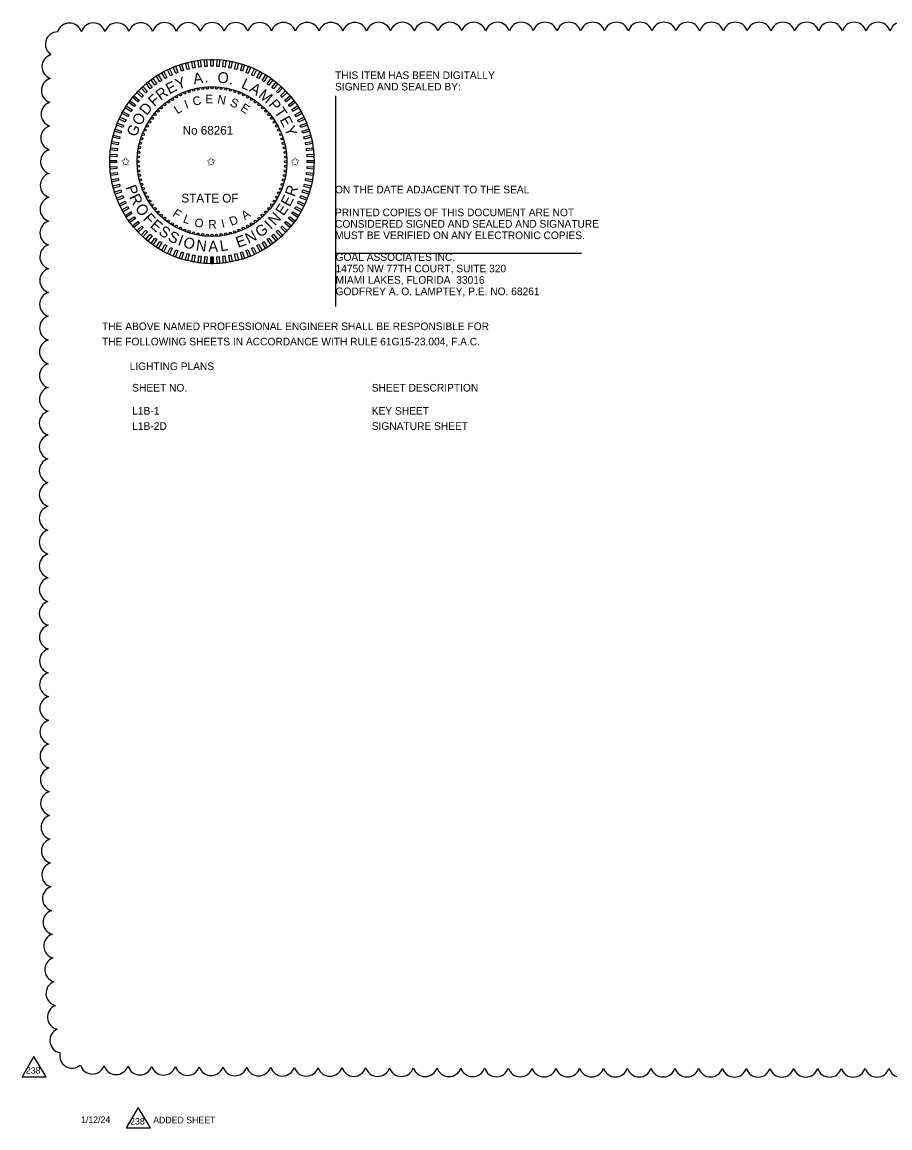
# Model space of a CAD drawing. Extents: x -811.2 to -755.6, y -2295.2 to -2235.1.
# Drawn here: x -811.23 to -803.27, y -2294.97 to -2284.82 of the extents above; entities that cross this region are included whole.
import ezdxf

# ---------------------------------------------------------------- set-up
doc = ezdxf.new("R2010")
doc.units = 0
for name, color, linetype in [('Cloud_dp', 7, 'Continuous'), ('Logo_dp', 7, 'Continuous'), ('NonPlottingEle_dp', 7, 'Continuous'), ('ScratchEle_dp', 7, 'Continuous'), ('TextMinor', 7, 'Continuous'), ('TextMisc', 7, 'Continuous'), ('TextNotes', 7, 'Continuous')]:
    doc.layers.add(name, color=color, linetype=linetype)

msp = doc.modelspace()

# ---------------------------------------------------------------- linework, layer by layer
at = {"layer": 'Cloud_dp'}
for points in [[(-811.125, -2294.318), (-811.233, -2294.506), (-811.012, -2294.506)], [(-810.168, -2294.785), (-810.276, -2294.973), (-810.055, -2294.973)]]:
    msp.add_lwpolyline(points, close=True, dxfattribs=at)
for centre, start, end in [((-810.798, -2284.941), 18.0566, 163.0566), ((-810.58, -2284.94), 17.7998, 162.7998), ((-810.362, -2284.939), 17.7187, 162.7187), ((-810.143, -2284.938), 17.6743, 162.6743), ((-809.925, -2284.937), 17.6451, 162.6451), ((-809.707, -2284.937), 17.624, 162.624), ((-809.488, -2284.936), 17.6079, 162.6079), ((-809.27, -2284.936), 17.5951, 162.5951), ((-809.052, -2284.936), 17.5845, 162.5845), ((-808.834, -2284.935), 17.5756, 162.5756), ((-808.615, -2284.935), 17.568, 162.568), ((-808.397, -2284.935), 17.5614, 162.5614), ((-808.179, -2284.935), 17.5556, 162.5556), ((-807.96, -2284.934), 17.5505, 162.5505), ((-807.742, -2284.934), 17.5459, 162.5459), ((-807.524, -2284.934), 17.5417, 162.5417), ((-807.305, -2284.934), 17.5379, 162.5379), ((-807.087, -2284.934), 17.5344, 162.5344), ((-806.869, -2284.934), 17.5313, 162.5313), ((-806.65, -2284.933), 17.5283, 162.5283), ((-806.432, -2284.933), 17.5256, 162.5256), ((-806.214, -2284.933), 17.5231, 162.5231), ((-805.995, -2284.933), 17.5207, 162.5207), ((-805.777, -2284.933), 17.5185, 162.5185), ((-805.559, -2284.933), 17.5164, 162.5164), ((-805.34, -2284.933), 17.5145, 162.5145), ((-805.122, -2284.933), 17.5126, 162.5126), ((-804.904, -2284.933), 17.5109, 162.5109), ((-804.685, -2284.933), 17.5092, 162.5092), ((-804.467, -2284.933), 17.5077, 162.5077), ((-804.249, -2284.933), 17.5062, 162.5062), ((-804.03, -2284.933), 17.5048, 162.5048), ((-803.812, -2284.933), 17.5034, 162.5034), ((-803.594, -2284.933), 17.5021, 162.5021), ((-803.375, -2284.933), 17.5009, 162.5009), ((-803.157, -2284.933), 17.5, 162.5), ((-810.905, -2285.022), 91.4771, 236.4771), ((-810.937, -2285.228), 105.908, 250.908), ((-810.942, -2285.446), 106.4168, 251.4168), ((-810.945, -2285.664), 106.6762, 251.6762), ((-810.948, -2285.882), 106.841, 251.841), ((-810.95, -2286.1), 106.9576, 251.9576), ((-810.952, -2286.318), 107.0457, 252.0457), ((-810.954, -2286.537), 107.1154, 252.1154), ((-810.955, -2286.755), 107.1722, 252.1722), ((-810.956, -2286.973), 107.2198, 252.2198), ((-810.957, -2287.192), 107.2603, 252.2603), ((-810.958, -2287.41), 107.2954, 252.2954), ((-810.959, -2287.628), 107.3262, 252.3262), ((-810.96, -2287.847), 107.3535, 252.3535), ((-810.96, -2288.065), 107.3779, 252.3779), ((-810.96, -2288.283), 107.3998, 252.3998), ((-810.961, -2288.501), 107.4198, 252.4198), ((-810.961, -2288.72), 107.438, 252.438), ((-810.961, -2288.938), 107.4547, 252.4547), ((-810.961, -2289.156), 107.4701, 252.4701), ((-810.962, -2289.375), 107.4843, 252.4843), ((-810.962, -2289.593), 107.499, 252.499), ((-810.961, -2289.811), 107.5356, 252.5356), ((-810.961, -2290.03), 107.5822, 252.5822), ((-810.961, -2290.248), 107.6325, 252.6325), ((-810.96, -2290.466), 107.6869, 252.6869), ((-810.959, -2290.685), 107.7461, 252.7461), ((-810.958, -2290.903), 107.8108, 252.8108), ((-810.957, -2291.121), 107.8818, 252.8818), ((-810.955, -2291.339), 107.9604, 252.9604), ((-810.954, -2291.558), 108.0479, 253.0479), ((-810.951, -2291.776), 108.1461, 253.1461), ((-810.949, -2291.994), 108.2576, 253.2576), ((-810.945, -2292.212), 108.3854, 253.3854), ((-810.942, -2292.431), 108.534, 253.534), ((-810.938, -2292.649), 108.7099, 253.7099), ((-810.932, -2292.867), 108.9225, 253.9225), ((-810.927, -2293.085), 109.1867, 254.1867), ((-810.92, -2293.303), 109.5275, 254.5275), ((-810.911, -2293.521), 109.9909, 254.9909), ((-810.9, -2293.738), 110.6749, 255.6749), ((-810.886, -2293.956), 111.8417, 256.8417), ((-810.864, -2294.171), 114.6718, 259.6718), ((-810.774, -2294.311), 166.2299, 311.2299), ((-810.588, -2294.365), 196.1072, 341.1072), ((-810.37, -2294.37), 196.5738, 341.5738), ((-810.152, -2294.373), 196.7877, 341.7877), ((-809.934, -2294.375), 196.9179, 341.9179), ((-809.715, -2294.377), 197.008, 342.008), ((-809.497, -2294.379), 197.075, 342.075), ((-809.279, -2294.381), 197.1274, 342.1274), ((-809.061, -2294.382), 197.1699, 342.1699), ((-808.842, -2294.383), 197.2052, 342.2052), ((-808.624, -2294.384), 197.2352, 342.2352), ((-808.406, -2294.385), 197.261, 342.261), ((-808.187, -2294.386), 197.2836, 342.2836), ((-807.969, -2294.387), 197.3036, 342.3036), ((-807.751, -2294.387), 197.3214, 342.3214), ((-807.532, -2294.388), 197.3374, 342.3374), ((-807.314, -2294.389), 197.3519, 342.3519), ((-807.096, -2294.389), 197.3651, 342.3651), ((-806.878, -2294.39), 197.3773, 342.3773), ((-806.659, -2294.39), 197.3884, 342.3884), ((-806.441, -2294.391), 197.3987, 342.3987), ((-806.223, -2294.391), 197.4083, 342.4083), ((-806.004, -2294.391), 197.4172, 342.4172), ((-805.786, -2294.392), 197.4256, 342.4256), ((-805.568, -2294.392), 197.4334, 342.4334), ((-805.349, -2294.392), 197.4407, 342.4407), ((-805.131, -2294.392), 197.4476, 342.4476), ((-804.913, -2294.392), 197.4542, 342.4542), ((-804.694, -2294.393), 197.4604, 342.4604), ((-804.476, -2294.393), 197.4662, 342.4662), ((-804.258, -2294.393), 197.4718, 342.4718), ((-804.039, -2294.393), 197.4771, 342.4771), ((-803.821, -2294.393), 197.4821, 342.4821), ((-803.603, -2294.393), 197.487, 342.487), ((-803.384, -2294.393), 197.4916, 342.4916), ((-803.166, -2294.393), 197.496, 342.496)]:
    msp.add_arc(centre, 0.114, start, end, dxfattribs=at)
at = {"layer": 'Logo_dp'}
for p, q in [((-809.5, -2287.037), (-809.5, -2286.974)), ((-809.49, -2287.037), (-809.49, -2286.974)), ((-809.48, -2287.037), (-809.48, -2286.974))]:
    msp.add_line(p, q, dxfattribs=at)
for points in [[(-809.698, -2285.249), (-809.717, -2285.254), (-809.733, -2285.194), (-809.713, -2285.189)], [(-809.644, -2285.238), (-809.664, -2285.242), (-809.676, -2285.18), (-809.656, -2285.176)], [(-809.59, -2285.23), (-809.61, -2285.232), (-809.618, -2285.17), (-809.598, -2285.168)], [(-809.535, -2285.225), (-809.555, -2285.227), (-809.559, -2285.164), (-809.539, -2285.163)], [(-809.48, -2285.224), (-809.5, -2285.224), (-809.5, -2285.162), (-809.48, -2285.162)], [(-809.425, -2285.227), (-809.445, -2285.225), (-809.441, -2285.163), (-809.421, -2285.164)], [(-809.37, -2285.232), (-809.39, -2285.23), (-809.383, -2285.168), (-809.363, -2285.17)], [(-809.316, -2285.242), (-809.336, -2285.238), (-809.324, -2285.177), (-809.304, -2285.18)], [(-809.263, -2285.254), (-809.282, -2285.249), (-809.267, -2285.189), (-809.247, -2285.194)], [(-809.95, -2285.355), (-809.967, -2285.366), (-810.001, -2285.313), (-809.984, -2285.302)], [(-809.903, -2285.328), (-809.92, -2285.337), (-809.951, -2285.283), (-809.933, -2285.273)], [(-809.853, -2285.303), (-809.872, -2285.312), (-809.898, -2285.255), (-809.88, -2285.247)], [(-809.803, -2285.282), (-809.822, -2285.289), (-809.845, -2285.231), (-809.826, -2285.224)], [(-809.751, -2285.264), (-809.77, -2285.27), (-809.789, -2285.211), (-809.77, -2285.205)], [(-809.21, -2285.27), (-809.229, -2285.264), (-809.21, -2285.205), (-809.191, -2285.211)], [(-809.159, -2285.289), (-809.177, -2285.282), (-809.154, -2285.224), (-809.136, -2285.231)], [(-809.108, -2285.312), (-809.127, -2285.303), (-809.1, -2285.247), (-809.082, -2285.255)], [(-809.06, -2285.337), (-809.077, -2285.328), (-809.047, -2285.273), (-809.03, -2285.283)], [(-809.013, -2285.366), (-809.03, -2285.355), (-808.996, -2285.302), (-808.979, -2285.313)], [(-810.04, -2285.419), (-810.056, -2285.431), (-810.095, -2285.383), (-810.08, -2285.37)], [(-809.996, -2285.385), (-810.013, -2285.397), (-810.049, -2285.347), (-810.033, -2285.335)], [(-808.968, -2285.397), (-808.984, -2285.385), (-808.947, -2285.335), (-808.931, -2285.347)], [(-808.925, -2285.432), (-808.94, -2285.419), (-808.9, -2285.371), (-808.885, -2285.383)], [(-810.158, -2285.534), (-810.171, -2285.549), (-810.219, -2285.509), (-810.206, -2285.494)], [(-810.121, -2285.493), (-810.135, -2285.508), (-810.18, -2285.465), (-810.167, -2285.45)], [(-810.082, -2285.454), (-810.096, -2285.468), (-810.139, -2285.423), (-810.124, -2285.409)], [(-808.884, -2285.468), (-808.898, -2285.455), (-808.856, -2285.409), (-808.841, -2285.423)], [(-808.845, -2285.508), (-808.859, -2285.493), (-808.814, -2285.45), (-808.8, -2285.465)], [(-808.809, -2285.549), (-808.822, -2285.534), (-808.774, -2285.494), (-808.761, -2285.51)], [(-810.223, -2285.622), (-810.234, -2285.639), (-810.287, -2285.605), (-810.276, -2285.588)], [(-810.192, -2285.577), (-810.204, -2285.593), (-810.254, -2285.556), (-810.243, -2285.54)], [(-808.776, -2285.593), (-808.788, -2285.577), (-808.738, -2285.54), (-808.726, -2285.556)], [(-808.746, -2285.639), (-808.757, -2285.622), (-808.704, -2285.588), (-808.693, -2285.606)], [(-810.278, -2285.717), (-810.286, -2285.736), (-810.343, -2285.709), (-810.334, -2285.691)], [(-810.252, -2285.669), (-810.262, -2285.686), (-810.316, -2285.656), (-810.307, -2285.639)], [(-808.718, -2285.687), (-808.728, -2285.669), (-808.673, -2285.639), (-808.664, -2285.657)], [(-808.694, -2285.736), (-808.703, -2285.718), (-808.646, -2285.691), (-808.638, -2285.709)], [(-810.319, -2285.819), (-810.325, -2285.838), (-810.385, -2285.819), (-810.379, -2285.8)], [(-810.3, -2285.768), (-810.307, -2285.786), (-810.365, -2285.763), (-810.358, -2285.745)], [(-808.673, -2285.787), (-808.68, -2285.768), (-808.622, -2285.745), (-808.615, -2285.764)], [(-808.655, -2285.839), (-808.661, -2285.819), (-808.602, -2285.8), (-808.595, -2285.819)], [(-810.335, -2285.872), (-810.34, -2285.891), (-810.401, -2285.876), (-810.396, -2285.856)], [(-808.64, -2285.892), (-808.645, -2285.872), (-808.585, -2285.856), (-808.58, -2285.876)], [(-810.357, -2285.979), (-810.36, -2285.999), (-810.421, -2285.992), (-810.419, -2285.972)], [(-810.348, -2285.925), (-810.352, -2285.945), (-810.413, -2285.933), (-810.409, -2285.914)], [(-808.629, -2285.945), (-808.632, -2285.925), (-808.571, -2285.914), (-808.567, -2285.934)], [(-808.621, -2286), (-808.623, -2285.98), (-808.561, -2285.972), (-808.559, -2285.992)], [(-810.365, -2286.089), (-810.365, -2286.109), (-810.428, -2286.109), (-810.428, -2286.089)], [(-810.363, -2286.034), (-810.364, -2286.054), (-810.426, -2286.05), (-810.425, -2286.03)], [(-808.616, -2286.054), (-808.617, -2286.034), (-808.555, -2286.03), (-808.554, -2286.051)], [(-808.615, -2286.109), (-808.615, -2286.089), (-808.553, -2286.089), (-808.553, -2286.109)], [(-810.364, -2286.144), (-810.363, -2286.164), (-810.425, -2286.168), (-810.426, -2286.148)], [(-810.36, -2286.199), (-810.357, -2286.219), (-810.419, -2286.227), (-810.421, -2286.207)], [(-808.623, -2286.219), (-808.621, -2286.199), (-808.559, -2286.207), (-808.561, -2286.227)], [(-808.617, -2286.164), (-808.616, -2286.144), (-808.554, -2286.148), (-808.555, -2286.168)], [(-810.352, -2286.253), (-810.348, -2286.273), (-810.409, -2286.285), (-810.413, -2286.265)], [(-810.34, -2286.307), (-810.335, -2286.327), (-810.396, -2286.342), (-810.401, -2286.323)], [(-808.645, -2286.327), (-808.64, -2286.307), (-808.58, -2286.323), (-808.585, -2286.342)], [(-808.632, -2286.273), (-808.629, -2286.253), (-808.567, -2286.265), (-808.571, -2286.285)], [(-810.325, -2286.36), (-810.319, -2286.379), (-810.379, -2286.398), (-810.385, -2286.379)], [(-810.307, -2286.412), (-810.3, -2286.431), (-810.358, -2286.454), (-810.366, -2286.435)], [(-808.68, -2286.431), (-808.673, -2286.412), (-808.615, -2286.435), (-808.622, -2286.454)], [(-808.661, -2286.379), (-808.655, -2286.36), (-808.595, -2286.379), (-808.602, -2286.399)], [(-810.286, -2286.463), (-810.278, -2286.481), (-810.334, -2286.507), (-810.343, -2286.489)], [(-810.262, -2286.512), (-810.252, -2286.53), (-810.307, -2286.56), (-810.317, -2286.542)], [(-808.728, -2286.53), (-808.719, -2286.512), (-808.664, -2286.542), (-808.674, -2286.56)], [(-808.703, -2286.481), (-808.694, -2286.463), (-808.638, -2286.489), (-808.646, -2286.508)], [(-810.234, -2286.56), (-810.224, -2286.577), (-810.276, -2286.61), (-810.287, -2286.593)], [(-810.204, -2286.605), (-810.192, -2286.622), (-810.243, -2286.658), (-810.255, -2286.642)], [(-808.788, -2286.622), (-808.776, -2286.605), (-808.726, -2286.642), (-808.738, -2286.659)], [(-808.757, -2286.577), (-808.746, -2286.56), (-808.693, -2286.593), (-808.704, -2286.61)], [(-810.171, -2286.649), (-810.158, -2286.665), (-810.206, -2286.705), (-810.219, -2286.689)], [(-810.135, -2286.691), (-810.121, -2286.706), (-810.167, -2286.748), (-810.18, -2286.734)], [(-808.859, -2286.706), (-808.845, -2286.691), (-808.8, -2286.734), (-808.814, -2286.748)], [(-808.822, -2286.665), (-808.81, -2286.649), (-808.761, -2286.689), (-808.774, -2286.705)], [(-810.097, -2286.73), (-810.082, -2286.744), (-810.125, -2286.789), (-810.139, -2286.776)], [(-810.056, -2286.767), (-810.04, -2286.78), (-810.08, -2286.828), (-810.096, -2286.815)], [(-810.013, -2286.801), (-809.996, -2286.813), (-810.033, -2286.864), (-810.049, -2286.852)], [(-808.984, -2286.813), (-808.968, -2286.801), (-808.931, -2286.852), (-808.947, -2286.864)], [(-808.94, -2286.78), (-808.925, -2286.767), (-808.885, -2286.815), (-808.9, -2286.828)], [(-808.899, -2286.744), (-808.884, -2286.73), (-808.841, -2286.776), (-808.856, -2286.79)], [(-809.968, -2286.833), (-809.951, -2286.843), (-809.984, -2286.896), (-810.001, -2286.885)], [(-809.921, -2286.861), (-809.903, -2286.871), (-809.933, -2286.926), (-809.951, -2286.916)], [(-809.872, -2286.887), (-809.854, -2286.895), (-809.88, -2286.952), (-809.898, -2286.943)], [(-809.822, -2286.909), (-809.803, -2286.917), (-809.826, -2286.975), (-809.845, -2286.967)], [(-809.77, -2286.928), (-809.751, -2286.935), (-809.77, -2286.994), (-809.79, -2286.988)], [(-809.229, -2286.935), (-809.21, -2286.928), (-809.191, -2286.988), (-809.21, -2286.994)], [(-809.177, -2286.917), (-809.159, -2286.909), (-809.136, -2286.967), (-809.154, -2286.975)], [(-809.127, -2286.895), (-809.109, -2286.887), (-809.082, -2286.943), (-809.1, -2286.952)], [(-809.077, -2286.871), (-809.06, -2286.861), (-809.03, -2286.916), (-809.047, -2286.926)], [(-809.03, -2286.844), (-809.013, -2286.833), (-808.979, -2286.885), (-808.996, -2286.896)], [(-809.718, -2286.944), (-809.698, -2286.949), (-809.714, -2287.01), (-809.733, -2287.005)], [(-809.664, -2286.957), (-809.644, -2286.961), (-809.656, -2287.022), (-809.676, -2287.018)], [(-809.61, -2286.966), (-809.59, -2286.969), (-809.598, -2287.031), (-809.618, -2287.028)], [(-809.555, -2286.972), (-809.535, -2286.973), (-809.539, -2287.035), (-809.559, -2287.034)], [(-809.5, -2286.974), (-809.48, -2286.974), (-809.48, -2287.037), (-809.5, -2287.037)], [(-809.445, -2286.973), (-809.425, -2286.972), (-809.421, -2287.034), (-809.441, -2287.036)], [(-809.391, -2286.969), (-809.371, -2286.966), (-809.363, -2287.028), (-809.383, -2287.031)], [(-809.336, -2286.961), (-809.316, -2286.957), (-809.305, -2287.018), (-809.324, -2287.022)], [(-809.282, -2286.949), (-809.263, -2286.944), (-809.247, -2287.005), (-809.267, -2287.01)]]:
    msp.add_lwpolyline(points, close=True, dxfattribs=at)
for centre in [(-809.816, -2285.505), (-809.778, -2285.486), (-809.739, -2285.469), (-809.699, -2285.455), (-809.658, -2285.443), (-809.617, -2285.434), (-809.574, -2285.427), (-809.532, -2285.423), (-809.49, -2285.422), (-809.447, -2285.423), (-809.405, -2285.427), (-809.363, -2285.434), (-809.321, -2285.443), (-809.28, -2285.455), (-809.24, -2285.47), (-809.201, -2285.486), (-809.163, -2285.506), (-809.953, -2285.605), (-809.922, -2285.577), (-809.888, -2285.551), (-809.853, -2285.527), (-809.127, -2285.528), (-809.091, -2285.551), (-809.058, -2285.578), (-809.026, -2285.606), (-810.038, -2285.701), (-810.012, -2285.667), (-809.984, -2285.635), (-808.996, -2285.636), (-808.968, -2285.668), (-808.942, -2285.701), (-810.103, -2285.81), (-810.084, -2285.772), (-810.062, -2285.736), (-808.918, -2285.737), (-808.896, -2285.773), (-808.877, -2285.811), (-810.134, -2285.889), (-810.12, -2285.849), (-808.86, -2285.85), (-808.846, -2285.89), (-810.162, -2286.014), (-810.155, -2285.972), (-810.146, -2285.93), (-808.834, -2285.931), (-808.825, -2285.973), (-808.818, -2286.015), (-810.168, -2286.099), (-810.166, -2286.056), (-808.814, -2286.057), (-808.813, -2286.1), (-810.166, -2286.141), (-810.162, -2286.184), (-810.156, -2286.226), (-808.825, -2286.227), (-808.818, -2286.185), (-808.814, -2286.142), (-810.146, -2286.267), (-810.135, -2286.308), (-808.846, -2286.309), (-808.834, -2286.268), (-810.12, -2286.348), (-810.103, -2286.387), (-810.084, -2286.425), (-808.897, -2286.426), (-808.877, -2286.388), (-808.86, -2286.349), (-810.062, -2286.462), (-810.039, -2286.497), (-810.012, -2286.531), (-808.968, -2286.532), (-808.942, -2286.498), (-808.918, -2286.463), (-809.984, -2286.563), (-809.954, -2286.593), (-809.922, -2286.621), (-809.059, -2286.622), (-809.027, -2286.593), (-808.997, -2286.563), (-809.889, -2286.647), (-809.854, -2286.671), (-809.817, -2286.693), (-809.779, -2286.712), (-809.74, -2286.729), (-809.241, -2286.729), (-809.202, -2286.712), (-809.164, -2286.693), (-809.128, -2286.672), (-809.092, -2286.648), (-809.7, -2286.743), (-809.659, -2286.755), (-809.618, -2286.765), (-809.576, -2286.771), (-809.533, -2286.775), (-809.49, -2286.777), (-809.448, -2286.775), (-809.406, -2286.771), (-809.364, -2286.765), (-809.322, -2286.756), (-809.281, -2286.744)]:
    msp.add_circle(centre, 0.01, dxfattribs=at)
at = {"layer": 'NonPlottingEle_dp'}
for radius in [0.938, 0.688]:
    msp.add_circle((-809.49, -2286.099), radius, dxfattribs=at)
at = {"layer": 'ScratchEle_dp'}
for p, q in [((-808.355, -2285.496), (-808.355, -2287.431)), ((-808.355, -2286.941), (-806.098, -2286.941))]:
    msp.add_line(p, q, dxfattribs=at)

# ---------------------------------------------------------------- texts
at = {"layer": 'Cloud_dp'}
for p in [(-811.198, -2294.476), (-810.241, -2294.943)]:
    msp.add_text('238', height=0.06, rotation=0, dxfattribs=at).set_placement(p)
at = {"layer": 'Logo_dp'}
for s, height, rotation, p in [('A', 0.1, 8.8088, (-809.655, -2285.389)), ('O', 0.1, 352.1877, (-809.445, -2285.371)), ('E', 0.1, 28.1055, (-809.881, -2285.483)), ('Y', 0.1, 21.0633, (-809.802, -2285.44)), ('.', 0.1, 1.0418, (-809.558, -2285.373)), ('.', 0.1, 343.5268, (-809.336, -2285.386)), ('L', 0.1, 334.6727, (-809.228, -2285.418)), ('A', 0.1, 328.4096, (-809.155, -2285.451)), ('F', 0.1, 42.3772, (-810.02, -2285.598)), ('R', 0.1, 35.9269, (-809.961, -2285.542)), ('C', 0.08, 12.2025, (-809.658, -2285.588)), ('E', 0.08, 0.4186, (-809.55, -2285.564)), ('N', 0.08, 349.2914, (-809.445, -2285.563)), ('M', 0.1, 320.6426, (-809.071, -2285.502)), ('D', 0.1, 50.8569, (-810.089, -2285.682)), ('L', 0.08, 30.4021, (-809.809, -2285.666)), ('I', 0.08, 20.0117, (-809.726, -2285.615)), ('S', 0.08, 337.0221, (-809.332, -2285.584)), ('E', 0.08, 325.8663, (-809.236, -2285.625)), ('P', 0.1, 311.1966, (-808.978, -2285.579)), ('T', 0.1, 304.4563, (-808.921, -2285.643)), ('O', 0.1, 59.5178, (-810.145, -2285.777)), ('E', 0.1, 297.6315, (-808.871, -2285.714)), ('G', 0.1, 68.0518, (-810.185, -2285.878)), ('Y', 0.1, 290.5893, (-808.828, -2285.793)), ('P', 0.1, 289.4055, (-810.285, -2286.334)), ('R', 0.1, 69.5134, (-808.73, -2286.429)), ('R', 0.1, 296.1458, (-810.252, -2286.425)), ('E', 0.1, 62.4712, (-808.776, -2286.52)), ('O', 0.1, 303.9671, (-810.2, -2286.526)), ('E', 0.1, 55.4289, (-808.833, -2286.604)), ('F', 0.1, 312.628, (-810.128, -2286.628)), ('F', 0.08, 328.7241, (-809.858, -2286.596)), ('L', 0.08, 339.2916, (-809.761, -2286.655)), ('O', 0.08, 349.6821, (-809.656, -2286.695)), ('D', 0.08, 22.0128, (-809.312, -2286.691)), ('A', 0.08, 34.4992, (-809.188, -2286.639)), ('N', 0.1, 47.1788, (-808.912, -2286.693)), ('E', 0.1, 319.0783, (-810.064, -2286.696)), ('S', 0.1, 326.1206, (-809.987, -2286.762)), ('R', 0.08, 2.3398, (-809.522, -2286.717)), ('I', 0.08, 14.2037, (-809.394, -2286.71)), ('G', 0.1, 35.1115, (-809.049, -2286.801)), ('I', 0.1, 43.6456, (-808.95, -2286.728)), ('S', 0.1, 333.193, (-809.902, -2286.819)), ('I', 0.1, 340.2654, (-809.81, -2286.864)), ('O', 0.1, 343.7986, (-809.762, -2286.882)), ('N', 0.1, 352.4595, (-809.641, -2286.914)), ('A', 0.1, 0.7097, (-809.523, -2286.927)), ('L', 0.1, 8.4767, (-809.41, -2286.924)), ('E', 0.1, 19.8191, (-809.25, -2286.892)), ('N', 0.1, 26.8614, (-809.154, -2286.857))]:
    msp.add_text(s, height=height, rotation=rotation, dxfattribs=at).set_placement(p)
for s, p in [('No 68261', (-809.759, -2285.852)), ('✩', (-810.325, -2286.137)), ('✩', (-809.54, -2286.137)), ('✩', (-808.769, -2286.137)), ('STATE OF', (-809.77, -2286.475))]:
    msp.add_text(s, height=0.08, dxfattribs=at).set_placement(p)
at = {"layer": 'TextMinor'}
for s, p in [('1/12/24', (-810.691, -2294.928)), ('ADDED SHEET', (-810.029, -2294.931))]:
    msp.add_text(s, height=0.06, dxfattribs=at).set_placement(p)
at = {"layer": 'TextMisc'}
for s, p in [('THIS ITEM HAS BEEN DIGITALLY', (-808.36, -2285.341)), ('SIGNED AND SEALED BY:', (-808.36, -2285.446)), ('ON THE DATE ADJACENT TO THE SEAL', (-808.36, -2286.391)), ('PRINTED COPIES OF THIS DOCUMENT ARE NOT ', (-808.36, -2286.601)), ('CONSIDERED SIGNED AND SEALED AND SIGNATURE ', (-808.36, -2286.706)), ('MUST BE VERIFIED ON ANY ELECTRONIC COPIES.', (-808.36, -2286.811)), ('GOAL ASSOCIATES INC.', (-808.355, -2287.011)), ('14750 NW 77TH COURT, SUITE 320', (-808.355, -2287.116)), ('MIAMI LAKES, FLORIDA  33016', (-808.355, -2287.221)), ('GODFREY A. O. LAMPTEY, P.E. NO. 68261', (-808.355, -2287.326)), ('THE ABOVE NAMED PROFESSIONAL ENGINEER SHALL BE RESPONSIBLE FOR ', (-810.499, -2287.647)), ('THE FOLLOWING SHEETS IN ACCORDANCE WITH RULE 61G15-23.004, F.A.C.', (-810.499, -2287.787)), ('LIGHTING PLANS', (-810.245, -2288.014))]:
    msp.add_text(s, height=0.07, dxfattribs=at).set_placement(p)
at = {"layer": 'TextNotes'}
for s, p in [('SHEET NO.', (-810.222, -2288.211)), ('SHEET DESCRIPTION', (-808.023, -2288.211)), ('L1B-1', (-810.222, -2288.423)), ('KEY SHEET', (-808.023, -2288.423)), ('L1B-2D', (-810.222, -2288.563)), ('SIGNATURE SHEET', (-808.023, -2288.563))]:
    msp.add_text(s, height=0.07, dxfattribs=at).set_placement(p)

doc.saveas('drawing.dxf')
